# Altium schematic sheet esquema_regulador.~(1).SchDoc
size A4
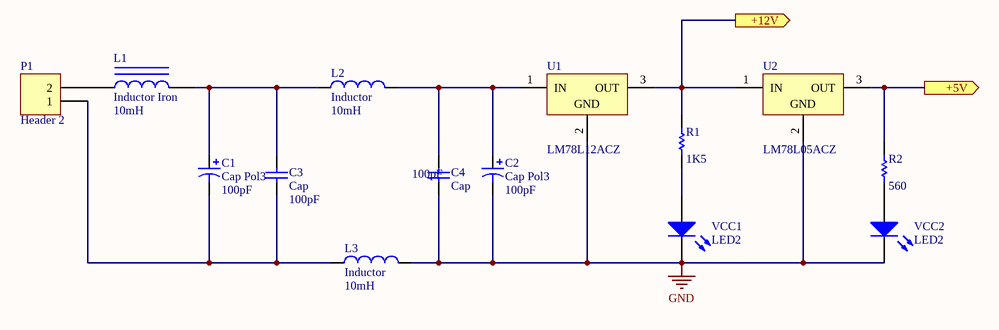
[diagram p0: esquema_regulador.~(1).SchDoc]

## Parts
C1  Cap Pol3  value 100pF  [1812]
C2  Cap Pol3  value 100pF  [1812]
C3  Cap  value 100pF  [RAD-0.3]
C4  Cap  value 100pF  [RAD-0.3]
L1  Inductor Iron  value 10mH  [AXIAL-0.9]
L2  Inductor  value 10mH  [0402-A]
L3  Inductor  value 10mH  [0402-A]
P1  Header 2  [HDR1X2]
R1  value 1K5  [1005[0402]]  (hidden comment: Carbon 1/8w 5%)
R2  value 560  [1005[0402]]  (hidden comment: Carbon 1/8w 5%)
U1  LM78L12ACZ  [T03B]
U2  LM78L05ACZ  [T03B]
VCC1  LED2  [3.2X1.6X1.1]
VCC2  LED2  [3.2X1.6X1.1]

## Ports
+5V (out), +12V (out)

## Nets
GND: C2.2 C4.1 L3.2 U1.2(GND) U2.2(GND) VCC1.2(K) VCC2.2(K)
+5V: R2.2 U2.3(OUT) ; port +5V
+12V: R1.2 U1.3(OUT) U2.1(IN) ; port +12V
NetC1_1: C1.1 C3.2 L1.2 L2.1
NetC1_2: C1.2 C3.1 L3.1 P1.1
NetC2_1: C2.1 C4.2 L2.2 U1.1(IN)
NetL1_1: L1.1 P1.2
NetR1_1: R1.1 VCC1.1(A)
NetR2_1: R2.1 VCC2.1(A)

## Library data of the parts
C1 C2 = Cap Pol3: Polarized Capacitor (Surface Mount)
C3 C4 = Cap: Capacitor
L1 = Inductor Iron: Magnetic-Core Inductor
L2 L3 = Inductor: Code_IEC: 1005
P1 = Header 2: Header, 2-Pin
R1 R2 = Res Semi: Semiconductor Resistor
U1 = LM78L12ACZ: 3-Terminal Positive Regulator; PackageDocument: 2000
U2 = LM78L05ACZ: 3-Terminal Positive Regulator; PackageDocument: 2000
VCC1 VCC2 = LED2: Typical RED, GREEN, YELLOW, AMBER GaAs LED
